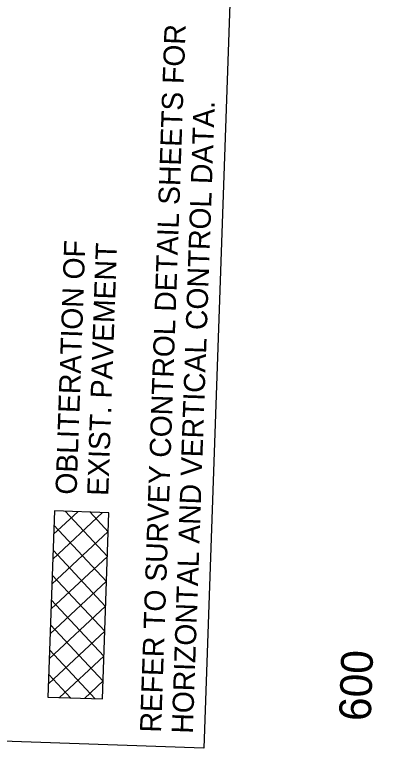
# Model space of a CAD drawing. Extents: x 634032 to 635126, y 289804 to 291423.
# Drawn here: x 634506.1 to 634615.3, y 289812.1 to 290020.2 of the extents above; entities that cross this region are included whole.
import ezdxf

# ---------------------------------------------------------------- set-up
doc = ezdxf.new("R2010")
doc.units = 0
for name, color, linetype in [('30', 7, 'Continuous'), ('Level 24', 7, 'Continuous'), ('Level 63', 7, 'Continuous'), ('R_Draft', 7, 'Continuous'), ('S_EDGE_PAVEMENT', 7, 'Continuous')]:
    doc.layers.add(name, color=color, linetype=linetype)

msp = doc.modelspace()

# ---------------------------------------------------------------- linework, layer by layer
at = {"layer": 'Level 63'}
msp.add_lwpolyline([(634559.67, 289812.08), (634032.37, 289830.49), (634077.11, 291111.87), (634126.48, 291110.15), (634129.89, 291207.79), (634129.89, 291207.79), (634137.41, 291423.16), (634615.34, 291406.47)], close=True, dxfattribs=at)
at = {"layer": 'S_EDGE_PAVEMENT'}
for p, q in [((634516.87, 289865.76), (634531.01, 289878.95)), ((634517.12, 289872.82), (634523.95, 289879.2)), ((634532.35, 289866.47), (634520.37, 289879.32)), ((634532.6, 289873.53), (634527.43, 289879.07)), ((634532.11, 289859.4), (634517.21, 289875.38)), ((634516.62, 289858.69), (634532.6, 289873.59)), ((634531.86, 289852.33), (634516.96, 289868.31)), ((634516.38, 289851.62), (634532.36, 289866.53)), ((634516.13, 289844.56), (634532.11, 289859.46)), ((634531.61, 289845.27), (634516.71, 289861.25)), ((634531.37, 289838.2), (634516.46, 289854.18)), ((634515.88, 289837.49), (634531.86, 289852.39)), ((634531.12, 289831.13), (634516.22, 289847.11)), ((634515.64, 289830.42), (634531.62, 289845.33)), ((634528.93, 289826.15), (634515.97, 289840.05)), ((634518.76, 289826.5), (634531.37, 289838.26)), ((634521.86, 289826.4), (634515.72, 289832.98)), ((634525.83, 289826.26), (634531.12, 289831.19))]:
    msp.add_line(p, q, dxfattribs=at)
msp.add_lwpolyline([(634530.94, 289826.08), (634532.79, 289878.89), (634517.35, 289879.43), (634515.5, 289826.62)], close=True, dxfattribs=at)

# ---------------------------------------------------------------- texts
at = {"layer": '30'}
msp.add_text('600', height=9, rotation=88, dxfattribs=at).set_placement((634606.96, 289819.71))
at = {"layer": 'Level 24'}
for s, p in [('REFER TO SURVEY CONTROL DETAIL SHEETS FOR', (634547.55, 289816.47)), ('HORIZONTAL AND VERTICAL CONTROL DATA.', (634556.55, 289816.16))]:
    msp.add_text(s, height=6, rotation=88.0044, dxfattribs=at).set_placement(p)
at = {"layer": 'R_Draft'}
for s, p in [('OBLITERATION OF', (634523.61, 289883.96)), ('EXIST. PAVEMENT', (634532.6, 289883.64))]:
    msp.add_text(s, height=6, rotation=88, dxfattribs=at).set_placement(p)

doc.saveas('drawing.dxf')
